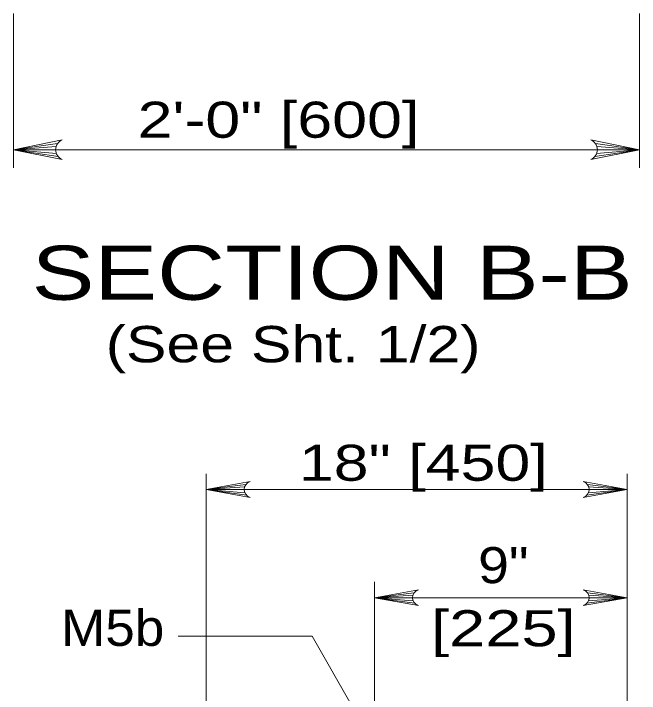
# Model space of a CAD drawing. Extents: x -1431.2 to -1397.2, y -1045.1 to -1001.1.
# Drawn here: x -1423.347 to -1420.591, y -1035.128 to -1032.135 of the extents above; entities that cross this region are included whole.
import ezdxf
from ezdxf.enums import TextEntityAlignment as Align

# ---------------------------------------------------------------- set-up
doc = ezdxf.new("R2010")
doc.units = 0
doc.header["$LTSCALE"] = 0.064
doc.layers.add('1', color=7, linetype='Continuous', lineweight=13)

msp = doc.modelspace()

# ---------------------------------------------------------------- linework, layer by layer
at = {"layer": '1'}
for p, q in [((-1423.34675, -1032.13508), (-1423.34675, -1032.81367)), ((-1420.59142, -1032.13508), (-1420.59142, -1032.81367)), ((-1423.15308, -1032.70725), (-1423.34675, -1032.73433)), ((-1423.15967, -1032.72058), (-1423.34675, -1032.73433)), ((-1423.16158, -1032.73433), (-1423.34675, -1032.73433)), ((-1423.15817, -1032.75175), (-1423.34675, -1032.73433)), ((-1423.15075, -1032.76425), (-1423.34675, -1032.73433)), ((-1423.34675, -1032.73433), (-1420.605, -1032.73433)), ((-1423.34675, -1032.73433), (-1420.59142, -1032.73433)), ((-1420.78742, -1032.76425), (-1420.59142, -1032.73433)), ((-1420.78517, -1032.70725), (-1420.59142, -1032.73433)), ((-1420.78, -1032.75175), (-1420.59142, -1032.73433)), ((-1420.77858, -1032.72058), (-1420.59142, -1032.73433)), ((-1420.77658, -1032.73433), (-1420.59142, -1032.73433)), ((-1422.49817, -1038.07125), (-1422.49817, -1034.16183)), ((-1420.646, -1035.6715), (-1420.646, -1034.16183)), ((-1422.32375, -1034.20858), (-1422.49817, -1034.2305)), ((-1422.32967, -1034.21942), (-1422.49817, -1034.2305)), ((-1420.646, -1034.2305), (-1422.49817, -1034.2305)), ((-1422.3315, -1034.2305), (-1422.49817, -1034.2305)), ((-1422.32842, -1034.24467), (-1422.49817, -1034.2305)), ((-1422.32175, -1034.25483), (-1422.49817, -1034.2305)), ((-1420.82233, -1034.25483), (-1420.646, -1034.2305)), ((-1420.82033, -1034.20858), (-1420.646, -1034.2305)), ((-1420.81567, -1034.24467), (-1420.646, -1034.2305)), ((-1420.81442, -1034.21942), (-1420.646, -1034.2305)), ((-1420.81258, -1034.2305), (-1420.646, -1034.2305)), ((-1421.75725, -1035.6715), (-1421.75725, -1034.63725)), ((-1421.58292, -1034.68492), (-1421.75725, -1034.70683)), ((-1421.58883, -1034.69575), (-1421.75725, -1034.70683)), ((-1421.59058, -1034.70683), (-1421.75725, -1034.70683)), ((-1421.5875, -1034.72092), (-1421.75725, -1034.70683)), ((-1421.58083, -1034.73108), (-1421.75725, -1034.70683)), ((-1420.646, -1034.70683), (-1421.75725, -1034.70683)), ((-1420.82233, -1034.73108), (-1420.646, -1034.70683)), ((-1420.82033, -1034.68492), (-1420.646, -1034.70683)), ((-1420.81567, -1034.72092), (-1420.646, -1034.70683)), ((-1420.81442, -1034.69575), (-1420.646, -1034.70683)), ((-1420.81258, -1034.70683), (-1420.646, -1034.70683)), ((-1422.62167, -1034.87683), (-1422.03208, -1034.87683)), ((-1421.06333, -1036.56683), (-1422.03208, -1034.87683))]:
    msp.add_line(p, q, dxfattribs=at)
for points in [[(-1423.13283, -1032.77708), (-1423.34675, -1032.73433), (-1423.13283, -1032.6915)], [(-1420.80542, -1032.77708), (-1420.59142, -1032.73433), (-1420.80542, -1032.6915)], [(-1422.30558, -1034.26517), (-1422.49817, -1034.2305), (-1422.30558, -1034.19592)], [(-1420.83858, -1034.26517), (-1420.646, -1034.2305), (-1420.83858, -1034.19592)], [(-1421.56467, -1034.7415), (-1421.75725, -1034.70683), (-1421.56467, -1034.67217)], [(-1420.83858, -1034.7415), (-1420.646, -1034.70683), (-1420.83858, -1034.67217)]]:
    msp.add_lwpolyline(points, dxfattribs=at)
for centre, start, end in [((-1423.11553, -1032.73427), 112.08782, 247.91395), ((-1420.82266, -1032.73427), 292.08605, 67.91218)]:
    msp.add_arc(centre, 0.04618, start, end, dxfattribs=at)
for centre, major_axis, start_param, end_param in [((-1422.29001, -1034.2305), (-0.04156, 0), 5.0978942, 7.4685073), ((-1420.8541, -1034.2305), (0.04156, 0), 5.0978633, 7.4684764), ((-1421.54912, -1034.7068), (-0.04156, 0), 5.0978942, 7.4685073), ((-1420.8541, -1034.7068), (0.04156, 0), 5.0978633, 7.4684764)]:
    msp.add_ellipse(centre, major_axis=major_axis, ratio=0.9, start_param=start_param, end_param=end_param, dxfattribs=at)

# ---------------------------------------------------------------- texts
for s, height, width, p in [('2\'-0" [600]', 0.1588, 1.3, (-1422.80067, -1032.68167)), ('SECTION B-B', 0.2382, 1.3, (-1423.26708, -1033.39525)), ('(See Sht. 1/2)', 0.16, 1.25, (-1422.94117, -1033.6705)), ('M5b', 0.1588, 1.1, (-1423.13767, -1034.91908))]:
    msp.add_text(s, height=height, dxfattribs=dict(at, width=width)).set_placement(p)
for s, width, p in [('18" [450]', 1.3, (-1421.543, -1034.19217)), ('9"', 1.15, (-1421.1905, -1034.643)), ('[225]', 1.35, (-1421.1905, -1034.92083))]:
    msp.add_text(s, height=0.1588, dxfattribs=dict(at, width=width)).set_placement(p, align=Align.CENTER)

doc.saveas('drawing.dxf')
